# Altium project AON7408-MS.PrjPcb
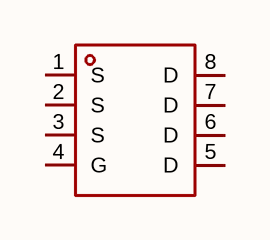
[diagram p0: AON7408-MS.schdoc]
1 sheet, 1 parts. Net scope: global (net labels, ports and power ports of the same name join across sheets).

## Sheet AON7408-MS.schdoc
size 127 x 101 mm

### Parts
Q?  aon7408-ms  [POWERPAK-1212-8_L3.0-W3.0-P0.65-LS3.3-BL]  (value not drawn)

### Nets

Not connected (* = marked no-connect by the designer): Q? 1(S) 2(S) 3(S) 4(G) 5(D) 6(D) 7(D) 8(D)

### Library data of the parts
Q? = aon7408-ms: 数量:1个N沟道;漏源电压(Vdss):30V;连续漏极电流(Id):20A;导通电阻(RDS(on)):15mΩ@10V;耗散功率(Pd):5.5W;阈值电压(Vgs(th)):1.5V;; Manufacturer: MSKSEMI(美森科); AddInBom: yes; ModelId: 74fc8db97a8d4d328d7f3b4acba39a5e; ModelTransform: 129.921,129.921,0,0,0,0,0,0,0; Number: 1个N沟道; Drain to Source Voltage: 30V; Current - Continuous Drain(Id): 20A; Pd - Power Dissipation: 5.5W; Gate Threshold Voltage (Vgs(th)): 1.5V; Gate Charge(Qg): 10nC; Input Capacitance(Ciss): 490pF; Reverse Transfer Capacitance (Crss@Vds): 61pF; Configuration: 独立式; Type: N沟道; Output Capacitance(Coss): 79pF; Vgs: ±20V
